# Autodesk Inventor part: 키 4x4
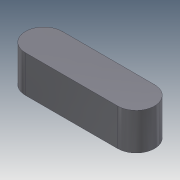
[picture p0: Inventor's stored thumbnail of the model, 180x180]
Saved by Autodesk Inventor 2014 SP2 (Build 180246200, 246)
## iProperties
Company: 한국ATC센터
Created: 2014-10
Part Number: 키 4x4
Document SubType Name: Modeling
Designer: KYOUNG IL JANG
Density: 1 g/cm^3
Mass: 0.210265 g
Surface Area: 2.35398 cm^2
Volume: 0.210265 cm^3
Material: 일반
Appearance: 강철 - 광택
Author: KYOUNG IL JANG
Revision Number: 1
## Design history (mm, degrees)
sketch "스케치1"
  geometry: L1 (-5, -2)-(5, -2); L2 (5, 2)-(-5, 2); A1 r 2 centre (5, 0) between (5, -2) and (5, 2); A2 r 2 centre (-5, 0) between (-5, 2) and (-5, -2); 2 further points
  constraints: 4 end point, 4 point on circle, 4 tangent, 2 centre point, 1 horizontal, 1 horizontal alignment, 1 midpoint, 1 parallel, 1 vertical alignment
  dimensions: "d0" = 4 distance between parallel lines of L1 L2; "d1" = 14 dimension on A1 A2
extrude "돌출1" new body sketch "스케치1" stored distance "d2" = 4; taper "d3" = 0 deg
node "솔리드1"
